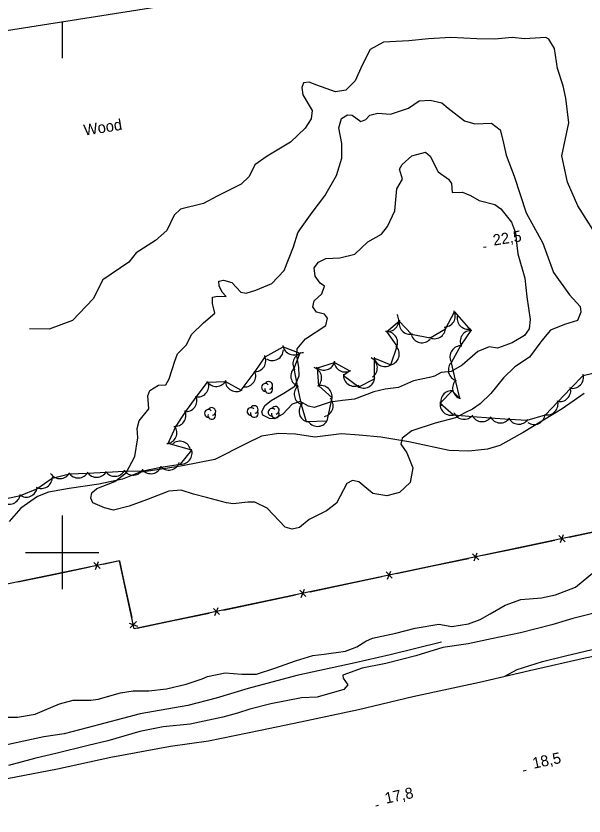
# Model space of a CAD drawing. Extents: x 643342 to 646936, y 5873857 to 5876103.
# Drawn here: x 645787.4 to 645941.9, y 5875728.4 to 5875945.7 of the extents above; entities that cross this region are included whole.
import ezdxf

# ---------------------------------------------------------------- set-up
doc = ezdxf.new("R2010")
doc.units = 0
for name, color, linetype in [('Niveau 1', 7, 'Continuous'), ('Niveau 2', 7, 'Continuous'), ('Niveau 22', 7, 'Continuous'), ('Niveau 25', 7, 'Continuous'), ('Niveau 3', 7, 'Continuous'), ('Niveau 37', 7, 'Continuous'), ('Niveau 4', 7, 'Continuous'), ('Niveau 44', 7, 'Continuous'), ('Niveau 60', 7, 'Continuous'), ('Niveau 61', 7, 'Continuous')]:
    doc.layers.add(name, color=color, linetype=linetype)

msp = doc.modelspace()

# ---------------------------------------------------------------- linework, layer by layer
at = {"layer": 'Niveau 1'}
for points in [[(645871.64, 5875879.82), (645875.45, 5875880.05), (645879.53, 5875881.06), (645883.06, 5875884.39), (645886.85, 5875886.41), (645888.41, 5875888.55), (645890.45, 5875892.76), (645890.95, 5875898.78), (645892.52, 5875901.37), (645891.69, 5875904.12), (645892.42, 5875905.42), (645895.01, 5875907.78), (645898.74, 5875908.75), (645900.08, 5875907.68), (645902.18, 5875903.38), (645905.02, 5875901.37), (645905.85, 5875900.18), (645906.06, 5875897.77), (645908.78, 5875897.89), (645911.03, 5875896.97), (645913.34, 5875895.59), (645917.58, 5875894.54), (645919.29, 5875893.33), (645922.19, 5875889.75), (645923.21, 5875886.79), (645923.59, 5875883.41), (645923.84, 5875881.12), (645925.74, 5875874.49), (645926.31, 5875869.39), (645927.22, 5875863.28), (645926.98, 5875860.76), (645925.72, 5875858.95), (645922.29, 5875856.9), (645918.37, 5875855.5), (645916.06, 5875855.84), (645913.01, 5875854.53), (645908.7, 5875850.88), (645905.75, 5875849.12), (645903.05, 5875848.83), (645901.23, 5875847.89), (645899.88, 5875847.51)], [(645899.88, 5875847.51), (645895.5, 5875846.58), (645891.39, 5875844.75), (645887.77, 5875844.37), (645884.71, 5875843.58), (645879.51, 5875841.64), (645876.18, 5875841.23), (645872.86, 5875840.76), (645868.53, 5875839.37), (645866.92, 5875839.72), (645864.69, 5875840.94), (645862.55, 5875840.3), (645860, 5875837.54), (645857.64, 5875836.24), (645856.35, 5875836.34), (645854.51, 5875837.24), (645854.29, 5875838.15), (645855.09, 5875839.92), (645856.8, 5875841.26), (645860.25, 5875843.25), (645863.23, 5875845.19), (645864.38, 5875847.98), (645864.3, 5875850.29), (645863.78, 5875853.42), (645863.87, 5875855.29), (645866.13, 5875858.02), (645871.67, 5875861.62), (645872.15, 5875863.59), (645871.32, 5875864.72), (645869.17, 5875865.24), (645868.13, 5875866.75), (645868.49, 5875868.3), (645870.6, 5875870.2), (645871.3, 5875872.36), (645870.16, 5875873.17), (645868.79, 5875875), (645868.48, 5875877.34), (645869.71, 5875878.8), (645871.64, 5875879.82)]]:
    msp.add_lwpolyline(points, dxfattribs=at)
at = {"layer": 'Niveau 2'}
for points in [[(645946.64, 5875884.03), (645940.15, 5875894.15), (645937.33, 5875900.59), (645935.83, 5875907.75), (645937.76, 5875916.66), (645936.89, 5875923.36), (645936.22, 5875926.77), (645934.66, 5875931.43), (645933.87, 5875936.91), (645932.25, 5875939.41), (645931.44, 5875939.85), (645925.65, 5875939.52), (645922.35, 5875939.87), (645917.49, 5875939.47), (645912.76, 5875939.55), (645905.61, 5875939.89), (645899.59, 5875939.49), (645894.23, 5875938.98), (645887.39, 5875938.6), (645883.76, 5875936.65), (645881.55, 5875932.41), (645879.63, 5875928.15), (645877.11, 5875925.62), (645874.31, 5875925.09), (645869.2, 5875926.98), (645867.14, 5875927.75), (645865.64, 5875927.54), (645865.14, 5875926.26), (645865.41, 5875924.32), (645867.93, 5875920.06), (645867.65, 5875917.82), (645866.07, 5875915.22), (645862.11, 5875911.49), (645855.71, 5875907.62), (645852.35, 5875905.29), (645850.83, 5875902.11), (645848.66, 5875900.08), (645842.14, 5875896.77), (645838.45, 5875894.81), (645832.15, 5875893.21), (645830.4, 5875891.58), (645828.41, 5875887.41), (645825.37, 5875884.77), (645820.09, 5875881.36), (645818.15, 5875878.83), (645811.03, 5875874.06), (645808.39, 5875868.84), (645802.84, 5875862.97), (645796.5, 5875860.66), (645791.09, 5875860.76)], [(645840.89, 5875869.31), (645842.25, 5875869.62), (645844.6, 5875869.47), (645843.48, 5875870.68), (645842.7, 5875872.4), (645842.57, 5875873.66), (645843.81, 5875873.97), (645846.1, 5875873.28), (645848.54, 5875870.7), (645850.03, 5875870.45), (645852.68, 5875871.25), (645856.97, 5875873.04), (645860.36, 5875876.59), (645862.86, 5875883.01), (645864.07, 5875886.85), (645864.82, 5875887.92), (645867.95, 5875892.37), (645871.4, 5875896.91), (645874.53, 5875902.4), (645875.99, 5875907.08), (645876.01, 5875911.08), (645875.25, 5875915.35), (645875.96, 5875917.92), (645877.54, 5875918.84), (645878.83, 5875918.8), (645881.17, 5875917.08), (645882.58, 5875917.57), (645883.66, 5875918.79), (645885.81, 5875919.37), (645889.28, 5875919.04), (645894.16, 5875920.72), (645897.03, 5875922.7), (645900.03, 5875922.9), (645903.21, 5875922.14), (645904.94, 5875920.7), (645909.33, 5875917.28), (645912.22, 5875916.43), (645916.74, 5875916.62), (645919.04, 5875914.77), (645919.82, 5875911.96), (645920.74, 5875907.88), (645922.89, 5875902.19), (645926.09, 5875892.21), (645930.62, 5875883.99), (645933.6, 5875876.06), (645937.95, 5875869.96), (645940.81, 5875866.78), (645940.98, 5875865.24), (645940.12, 5875863), (645936.51, 5875861.92), (645932.72, 5875860.41), (645930.35, 5875857.6), (645927.07, 5875853.02), (645923.04, 5875850.44), (645919.94, 5875847.38), (645916.57, 5875843.13), (645913.62, 5875840.32), (645911.56, 5875838.88), (645909.61, 5875838.04)], [(645909.61, 5875838.04), (645906.92, 5875836.59), (645901.37, 5875835.13), (645895.06, 5875833.06), (645892.43, 5875831.04), (645892.03, 5875829.37), (645893.69, 5875827.05), (645895.31, 5875822.98), (645894.64, 5875818.95), (645891.73, 5875816.26), (645888.28, 5875815.31), (645884.47, 5875816.01), (645880.62, 5875819.15), (645878.95, 5875819.5), (645877.4, 5875818.75), (645874.56, 5875813.33), (645871.87, 5875811.3), (645867.11, 5875808.94), (645864.5, 5875806.74), (645862.5, 5875806.3), (645860.58, 5875806.85), (645855.76, 5875811.98), (645852.37, 5875813.59), (645850.44, 5875813.62), (645846.47, 5875813.2), (645844.69, 5875813.48), (645839.23, 5875814.87), (645835.74, 5875815.78), (645832.36, 5875816.88), (645829, 5875816.64), (645822.91, 5875814.25), (645818.2, 5875812.52), (645813.94, 5875811.49), (645811.54, 5875812.11), (645808.36, 5875813.46), (645807.81, 5875814.68), (645808.06, 5875816.16), (645809.39, 5875817.35), (645814.31, 5875819.26), (645817.38, 5875821.57), (645819.75, 5875826.06), (645820.54, 5875831.08), (645820.38, 5875833.62), (645820.97, 5875835.72), (645823.52, 5875839.01), (645823.31, 5875842.53), (645823.79, 5875843.98), (645826.14, 5875845.39), (645828.17, 5875845.54), (645829.1, 5875847.1), (645830.61, 5875851.96), (645831.39, 5875853.9), (645833.79, 5875856.42), (645835.18, 5875859.18), (645838.39, 5875862.37), (645841.48, 5875865.01), (645840.9, 5875867.57), (645840.89, 5875869.31)], [(645934.1, 5875788.41), (645939.53, 5875790.56), (645944.73, 5875794.78)], [(645780.99, 5875755.24), (645787.89, 5875755.21), (645792.66, 5875756.01), (645795.22, 5875757.16), (645799.25, 5875758.81), (645803, 5875759.79), (645807.79, 5875759.83), (645809.81, 5875760.11), (645815.81, 5875761.85), (645819.32, 5875762.4), (645823.59, 5875762.33), (645828.38, 5875762.95), (645833.73, 5875764.22), (645838.02, 5875765.67), (645839.53, 5875766.3), (645844.33, 5875767.27), (645848.81, 5875766.93), (645852.85, 5875766.89), (645857.81, 5875768.53), (645863.44, 5875770.53), (645868.12, 5875772.01), (645871.18, 5875772.34), (645877.06, 5875773.14), (645880.14, 5875774.34), (645882.54, 5875775.88), (645884.38, 5875776.71), (645890.66, 5875778.08), (645896, 5875779.41), (645902.43, 5875780.5), (645905.95, 5875779.88), (645910.43, 5875780.53), (645913.63, 5875781.74), (645916.38, 5875783.32), (645920.39, 5875785.61), (645924.71, 5875787.23), (645930.33, 5875787.66), (645934.1, 5875788.41)], [(645948.47, 5875784.47), (645938.86, 5875782.05), (645933.09, 5875780.33), (645924.63, 5875778.09), (645916.74, 5875776.49), (645910.4, 5875775.18), (645903.5, 5875774.15), (645896.16, 5875771.86), (645887.97, 5875769.76), (645881.51, 5875768.49)], [(645920.33, 5875766.37), (645923.7, 5875768.19), (645930.58, 5875770.38), (645936.83, 5875771.91), (645945.59, 5875773.95)], [(645881.51, 5875768.49), (645876.33, 5875766.66), (645876.37, 5875765.79), (645877.68, 5875764.01), (645876.59, 5875762.72), (645869.28, 5875760.66), (645865.03, 5875760.5), (645856.68, 5875758.8), (645851.05, 5875757.39), (645847.63, 5875756.31), (645843.65, 5875755.25), (645834.83, 5875753.29), (645827.48, 5875752.57), (645821.13, 5875751.31), (645812.4, 5875748.81), (645807.1, 5875747.55), (645798.28, 5875745.33), (645792.86, 5875744.11), (645785.42, 5875742.09)]]:
    msp.add_lwpolyline(points, dxfattribs=at)
at = {"layer": 'Niveau 22'}
for points in [[(645941.92, 5875843.13), (645935.96, 5875839), (645925.36, 5875832.52), (645918.97, 5875829.05), (645915.59, 5875828), (645910.51, 5875827.46), (645905.23, 5875827.71), (645894.24, 5875830.03), (645886.63, 5875831.32), (645880.74, 5875831.86), (645875.93, 5875832.16), (645868.69, 5875831.27), (645863.47, 5875832.11), (645858.79, 5875832.31), (645854.21, 5875831.6), (645849.89, 5875829.51), (645841.5, 5875825.25), (645832.72, 5875823.51), (645825.84, 5875822.43), (645820.91, 5875821.67), (645816.44, 5875819.92), (645809.94, 5875818.53), (645801.91, 5875817.33), (645796.29, 5875816.39), (645793.28, 5875815.14), (645788.72, 5875811.98)], [(645788.72, 5875811.98), (645785.61, 5875808.39)]]:
    msp.add_lwpolyline(points, dxfattribs=at)
at = {"layer": 'Niveau 25'}
msp.add_lwpolyline([(645735, 5875727.48), (645752.7, 5875731.47), (645770.29, 5875735.32), (645782.61, 5875738.14), (645798.77, 5875741.14), (645813.27, 5875744.32), (645829.42, 5875747.32), (645839.78, 5875748.77), (645853.95, 5875751.67), (645864.79, 5875753.99), (645880.55, 5875757.3), (645895.34, 5875760.85), (645913.48, 5875764.76), (645927.02, 5875767.94), (645942.17, 5875771.3), (645957.91, 5875774.6), (645975.77, 5875778.71), (645993.69, 5875783.29), (646008.47, 5875786.72)], dxfattribs=at)
at = {"layer": 'Niveau 3'}
for p, q in [((645914.49, 5875882.92), (645915.28, 5875883.04)), ((645925.35, 5875740.63), (645926.14, 5875740.8)), ((645885.23, 5875731.13), (645886.01, 5875731.3))]:
    msp.add_line(p, q, dxfattribs=at)
at = {"layer": 'Niveau 37'}
for points in [[(646156.26, 5875850.21), (646086.41, 5875835.45), (645993.12, 5875815.85), (645903.06, 5875796.81), (645819.6, 5875779.21), (645815.58, 5875797.71), (645725.88, 5875779.09), (645656.81, 5875764.27)], [(645935.44, 5875802.63), (645936.3, 5875804.85)], [(645937.81, 5875804.15), (645947.6, 5875806.22)], [(645924.12, 5875801.26), (645933.9, 5875803.33)], [(645935.02, 5875804.58), (645936.71, 5875802.9)], [(645914.33, 5875799.19), (645924.12, 5875801.26)], [(645900.64, 5875796.29), (645910.42, 5875798.36)], [(645911.54, 5875799.62), (645913.23, 5875797.94)], [(645911.96, 5875797.67), (645912.82, 5875799.89)], [(645808.63, 5875797.28), (645810.3, 5875795.59)], [(645809.03, 5875795.33), (645809.9, 5875797.55)], [(645811.14, 5875796.81), (645815.58, 5875797.74)], [(645815.58, 5875797.71), (645816.8, 5875792.09)], [(645890.85, 5875794.23), (645900.64, 5875796.29)], [(645787.91, 5875791.96), (645797.71, 5875794)], [(645797.71, 5875794), (645807.5, 5875796.03)], [(645888.06, 5875794.66), (645889.75, 5875792.98)], [(645888.47, 5875792.71), (645889.33, 5875794.93)], [(645816.8, 5875792.09), (645818.92, 5875782.32)], [(645877.15, 5875791.34), (645886.94, 5875793.41)], [(645864.58, 5875789.71), (645866.26, 5875788.03)], [(645864.99, 5875787.76), (645865.85, 5875789.98)], [(645867.37, 5875789.28), (645877.15, 5875791.34)], [(645853.67, 5875786.39), (645863.45, 5875788.46)], [(645843.88, 5875784.33), (645853.67, 5875786.39)], [(645830.19, 5875781.44), (645839.97, 5875783.5)], [(645841.1, 5875784.76), (645842.78, 5875783.08)], [(645841.51, 5875782.81), (645842.37, 5875785.03)], [(645820.19, 5875781.2), (645818.51, 5875779.51)], [(645820.4, 5875779.38), (645830.19, 5875781.44)], [(645818.24, 5875780.78), (645820.47, 5875779.93)]]:
    msp.add_lwpolyline(points, dxfattribs=at)
at = {"layer": 'Niveau 4'}
msp.add_lwpolyline([(645903.13, 5875775.55), (645889.12, 5875772.19), (645879.65, 5875770.02), (645863.77, 5875766.58), (645850.6, 5875762.97), (645841.87, 5875760.41), (645834.13, 5875758.42), (645821.16, 5875756.1), (645806.82, 5875752.36), (645800.57, 5875750.65), (645795.05, 5875749.83), (645782.01, 5875747.04), (645778.4, 5875745.72), (645775.4, 5875745.4), (645766.19, 5875743.96), (645758.88, 5875742.25), (645744.54, 5875739.56), (645733.3, 5875737.43), (645718.22, 5875733.96), (645705.61, 5875731.45), (645698.18, 5875729.73), (645684.8, 5875726.78)], dxfattribs=at)
at = {"layer": 'Niveau 44'}
for points in [[(645894.99, 5875859.28), (645900.02, 5875858.29), (645904.19, 5875860.77), (645906.64, 5875865.37), (645911.07, 5875860.29), (645908.38, 5875856.25), (645905.71, 5875851.47), (645906.82, 5875846.74), (645907.97, 5875841.87), (645905.99, 5875843.92), (645902.75, 5875840.54), (645906.38, 5875837.32), (645911.6, 5875836.92), (645916.45, 5875836.58), (645921.58, 5875836.22), (645926.42, 5875835.88), (645931.4, 5875837.35), (645934.74, 5875840.87), (645938.3, 5875844.58), (645941.67, 5875848.08), (645946.85, 5875849.28)], [(645783.62, 5875814.38), (645788.65, 5875815.44), (645793.14, 5875817.3), (645797.32, 5875820.15), (645802.01, 5875821.36), (645806.86, 5875821.54), (645812.01, 5875821.75), (645816.85, 5875822.05), (645822.05, 5875822.17), (645826.81, 5875823.12), (645832.12, 5875823.99), (645835.23, 5875827.72), (645828.8, 5875829.59), (645830.79, 5875834.01), (645833.58, 5875838.24), (645836.45, 5875842.16), (645839.55, 5875846.21), (645844.4, 5875846.45), (645848.67, 5875844.02), (645852.5, 5875849.1), (645855.18, 5875853.15), (645860.09, 5875855.85), (645864.62, 5875854.11), (645862.96, 5875849.98), (645863.86, 5875845.21), (645865.01, 5875840.18), (645866.37, 5875835.52), (645872.02, 5875835.73), (645873.35, 5875842), (645869.74, 5875845.24), (645869.38, 5875850.1), (645874.01, 5875851.55), (645878.2, 5875849.28), (645876.47, 5875848.08), (645880.61, 5875844.93), (645884.93, 5875847.14), (645884.86, 5875852.73), (645889.37, 5875850.96), (645891.04, 5875856.04), (645888.23, 5875860), (645891.64, 5875862.79), (645894.99, 5875859.28)]]:
    msp.add_lwpolyline(points, dxfattribs=at)
for centre, radius, start, end in [((645903.87, 5875864.22), 3, 268.5868, 28.5647), ((645903.87, 5875864.22), 3, 268.5868, 28.5647), ((645903.87, 5875864.22), 3, 268.5868, 28.5647), ((645888.51, 5875863), 3, 273.2391, 33.217), ((645888.51, 5875863), 3, 273.2391, 33.217), ((645888.51, 5875863), 3, 273.2391, 33.217), ((645910.34, 5875863.62), 3, 163.6389, 283.6168), ((645910.34, 5875863.62), 3, 163.6389, 283.6168), ((645910.34, 5875863.62), 3, 163.6389, 283.6168), ((645894.59, 5875862.25), 3, 163.6761, 283.6541), ((645894.59, 5875862.25), 3, 163.6761, 283.6541), ((645894.59, 5875862.25), 3, 163.6761, 283.6541), ((645888.19, 5875857), 3, 335.401, 95.379), ((645888.19, 5875857), 3, 335.401, 95.379), ((645888.19, 5875857), 3, 335.401, 95.379), ((645901.2, 5875861.04), 3, 240.8288, 0.8068), ((645901.2, 5875861.04), 3, 240.8288, 0.8068), ((645901.2, 5875861.04), 3, 240.8288, 0.8068), ((645911.19, 5875857.29), 3, 86.3436, 206.3216), ((645911.19, 5875857.29), 3, 86.3436, 206.3216), ((645911.19, 5875857.29), 3, 86.3436, 206.3216), ((645897.8, 5875859.95), 3, 197.1344, 317.1124), ((645897.8, 5875859.95), 3, 197.1344, 317.1124), ((645897.8, 5875859.95), 3, 197.1344, 317.1124), ((645857.16, 5875855.12), 3, 238.1313, 358.1093), ((645857.16, 5875855.12), 3, 238.1313, 358.1093), ((645857.16, 5875855.12), 3, 238.1313, 358.1093), ((645862.98, 5875856.63), 3, 189.0379, 309.0159), ((645862.98, 5875856.63), 3, 189.0379, 309.0159), ((645862.98, 5875856.63), 3, 189.0379, 309.0159), ((645888.65, 5875853.87), 3, 286.9533, 46.9312), ((645888.65, 5875853.87), 3, 286.9533, 46.9312), ((645888.65, 5875853.87), 3, 286.9533, 46.9312), ((645908.42, 5875853.13), 3, 86.3436, 206.3216), ((645908.42, 5875853.13), 3, 86.3436, 206.3216), ((645908.42, 5875853.13), 3, 86.3436, 206.3216), ((645852.37, 5875852.1), 3, 266.5586, 26.5366), ((645852.37, 5875852.1), 3, 266.5586, 26.5366), ((645852.37, 5875852.1), 3, 266.5586, 26.5366), ((645865.73, 5875851.23), 3, 92.6679, 212.6459), ((645865.73, 5875851.23), 3, 92.6679, 212.6459), ((645865.73, 5875851.23), 3, 92.6679, 212.6459), ((645882.68, 5875850.13), 3, 303.3789, 63.3568), ((645882.68, 5875850.13), 3, 303.3789, 63.3568), ((645882.68, 5875850.13), 3, 303.3789, 63.3568), ((645887.76, 5875853.49), 3, 188.557, 308.535), ((645887.76, 5875853.49), 3, 188.557, 308.535), ((645887.76, 5875853.49), 3, 188.557, 308.535), ((645871.17, 5875852.51), 3, 227.3613, 347.3393), ((645871.17, 5875852.51), 3, 227.3613, 347.3393), ((645871.17, 5875852.51), 3, 227.3613, 347.3393), ((645876.92, 5875852), 3, 181.2468, 301.2247), ((645876.92, 5875852), 3, 181.2468, 301.2247), ((645876.92, 5875852), 3, 181.2468, 301.2247), ((645907.98, 5875849.51), 3, 133.2394, 253.2173), ((645907.98, 5875849.51), 3, 133.2394, 253.2173), ((645907.98, 5875849.51), 3, 133.2394, 253.2173), ((645849.61, 5875847.92), 3, 266.5586, 26.5366), ((645849.61, 5875847.92), 3, 266.5586, 26.5366), ((645849.61, 5875847.92), 3, 266.5586, 26.5366), ((645865.15, 5875847.92), 3, 130.6612, 250.6391), ((645865.15, 5875847.92), 3, 130.6612, 250.6391), ((645865.15, 5875847.92), 3, 130.6612, 250.6391), ((645867.52, 5875847.38), 3, 310.7379, 70.7159), ((645867.52, 5875847.38), 3, 310.7379, 70.7159), ((645867.52, 5875847.38), 3, 310.7379, 70.7159), ((645879.46, 5875848.12), 3, 174.7108, 294.6888), ((645879.46, 5875848.12), 3, 174.7108, 294.6888), ((645879.46, 5875848.12), 3, 174.7108, 294.6888), ((645938.71, 5875847.55), 3, 256.1494, 16.1273), ((645938.71, 5875847.55), 3, 256.1494, 16.1273), ((645938.71, 5875847.55), 3, 256.1494, 16.1273), ((645836.86, 5875845.22), 3, 257.8089, 17.7868), ((645836.86, 5875845.22), 3, 257.8089, 17.7868), ((645836.86, 5875845.22), 3, 257.8089, 17.7868), ((645841.89, 5875848.09), 3, 212.8172, 332.7952), ((645841.89, 5875848.09), 3, 212.8172, 332.7952), ((645841.89, 5875848.09), 3, 212.8172, 332.7952), ((645847.33, 5875846.7), 3, 182.5344, 302.5124), ((645847.33, 5875846.7), 3, 182.5344, 302.5124), ((645847.33, 5875846.7), 3, 182.5344, 302.5124), ((645856.15, 5875845.34), 1.05, 282.2692, 149.7263), ((645881.97, 5875847.61), 3, 237.0883, 357.0663), ((645881.97, 5875847.61), 3, 237.0883, 357.0663), ((645881.97, 5875847.61), 3, 237.0883, 357.0663), ((645909.13, 5875844.64), 3, 133.2394, 253.2173), ((645909.13, 5875844.64), 3, 133.2394, 253.2173), ((645909.13, 5875844.64), 3, 133.2394, 253.2173), ((645855.25, 5875844.81), 1.05, 44.1154, 269.804), ((645856.15, 5875844.29), 1.05, 166.9369, 29.6212), ((645866.07, 5875843.01), 3, 130.6612, 250.6391), ((645866.07, 5875843.01), 3, 130.6612, 250.6391), ((645866.07, 5875843.01), 3, 130.6612, 250.6391), ((645870.36, 5875842.31), 3, 348.0533, 108.0312), ((645870.36, 5875842.31), 3, 348.0533, 108.0312), ((645870.36, 5875842.31), 3, 348.0533, 108.0312), ((645905.9, 5875840.92), 3, 82.3567, 202.3346), ((645905.9, 5875840.92), 3, 82.3567, 202.3346), ((645905.9, 5875840.92), 3, 82.3567, 202.3346), ((645935.25, 5875843.95), 3, 256.1494, 16.1273), ((645935.25, 5875843.95), 3, 256.1494, 16.1273), ((645935.25, 5875843.95), 3, 256.1494, 16.1273), ((645833.6, 5875841.24), 3, 263.7728, 23.7507), ((645833.6, 5875841.24), 3, 263.7728, 23.7507), ((645833.6, 5875841.24), 3, 263.7728, 23.7507), ((645870.66, 5875839.85), 3, 283.2232, 43.2012), ((645870.66, 5875839.85), 3, 283.2232, 43.2012), ((645870.66, 5875839.85), 3, 283.2232, 43.2012), ((645852.23, 5875838.8), 1.05, 282.2692, 149.7263), ((645857.94, 5875838.59), 1.05, 282.2692, 149.7263), ((645867.39, 5875838.34), 3, 136.1943, 256.1723), ((645867.39, 5875838.34), 3, 136.1943, 256.1723), ((645867.39, 5875838.34), 3, 136.1943, 256.1723), ((645905.73, 5875840.25), 3, 168.3669, 288.3448), ((645905.73, 5875840.25), 3, 168.3669, 288.3448), ((645905.73, 5875840.25), 3, 168.3669, 288.3448), ((645931.79, 5875840.32), 3, 256.5833, 16.5612), ((645931.79, 5875840.32), 3, 256.5833, 16.5612), ((645931.79, 5875840.32), 3, 256.5833, 16.5612), ((645830.64, 5875837.21), 3, 263.7728, 23.7507), ((645830.64, 5875837.21), 3, 263.7728, 23.7507), ((645830.64, 5875837.21), 3, 263.7728, 23.7507), ((645839.78, 5875837.74), 1.05, 44.1154, 269.804), ((645840.68, 5875837.22), 1.05, 166.9369, 29.6212), ((645840.68, 5875838.27), 1.05, 282.2692, 149.7263), ((645851.33, 5875838.27), 1.05, 44.1154, 269.804), ((645852.23, 5875837.75), 1.05, 166.9369, 29.6212), ((645857.04, 5875838.06), 1.05, 44.1154, 269.804), ((645857.94, 5875837.54), 1.05, 166.9369, 29.6212), ((645909.28, 5875839.14), 3, 202.432, 322.41), ((645909.28, 5875839.14), 3, 202.432, 322.41), ((645909.28, 5875839.14), 3, 202.432, 322.41), ((645928.29, 5875837.73), 3, 235.1539, 355.1318), ((645928.29, 5875837.73), 3, 235.1539, 355.1318), ((645928.29, 5875837.73), 3, 235.1539, 355.1318), ((645869.42, 5875837.23), 3, 216.0779, 336.0558), ((645869.42, 5875837.23), 3, 216.0779, 336.0558), ((645869.42, 5875837.23), 3, 216.0779, 336.0558), ((645914.15, 5875838.51), 3, 205.9737, 325.9516), ((645914.15, 5875838.51), 3, 205.9737, 325.9516), ((645914.15, 5875838.51), 3, 205.9737, 325.9516), ((645919.14, 5875838.16), 3, 205.9737, 325.9516), ((645919.14, 5875838.16), 3, 205.9737, 325.9516), ((645919.14, 5875838.16), 3, 205.9737, 325.9516), ((645924.12, 5875837.81), 3, 205.9737, 325.9516), ((645924.12, 5875837.81), 3, 205.9737, 325.9516), ((645924.12, 5875837.81), 3, 205.9737, 325.9516), ((645828.18, 5875832.53), 3, 275.7711, 35.749), ((645828.18, 5875832.53), 3, 275.7711, 35.749), ((645828.18, 5875832.53), 3, 275.7711, 35.749), ((645831.97, 5875827.2), 3, 11.0625, 131.0405), ((645831.97, 5875827.2), 3, 11.0625, 131.0405), ((645831.97, 5875827.2), 3, 11.0625, 131.0405), ((645832.32, 5875826.99), 3, 260.1003, 20.0782), ((645832.32, 5875826.99), 3, 260.1003, 20.0782), ((645832.32, 5875826.99), 3, 260.1003, 20.0782), ((645828.99, 5875825.34), 3, 221.1937, 341.1716), ((645828.99, 5875825.34), 3, 221.1937, 341.1716), ((645828.99, 5875825.34), 3, 221.1937, 341.1716), ((645814.32, 5875823.66), 3, 213.5308, 333.5087), ((645814.32, 5875823.66), 3, 213.5308, 333.5087), ((645814.32, 5875823.66), 3, 213.5308, 333.5087), ((645819.31, 5875823.97), 3, 213.5308, 333.5087), ((645819.31, 5875823.97), 3, 213.5308, 333.5087), ((645819.31, 5875823.97), 3, 213.5308, 333.5087), ((645824.09, 5875824.37), 3, 221.1937, 341.1716), ((645824.09, 5875824.37), 3, 221.1937, 341.1716), ((645824.09, 5875824.37), 3, 221.1937, 341.1716), ((645794.33, 5875820.36), 3, 241.9118, 1.8898), ((645794.33, 5875820.36), 3, 241.9118, 1.8898), ((645794.33, 5875820.36), 3, 241.9118, 1.8898), ((645799.38, 5875823.03), 3, 212.0468, 332.0247), ((645799.38, 5875823.03), 3, 212.0468, 332.0247), ((645799.38, 5875823.03), 3, 212.0468, 332.0247), ((645804.37, 5875823.21), 3, 212.0468, 332.0247), ((645804.37, 5875823.21), 3, 212.0468, 332.0247), ((645804.37, 5875823.21), 3, 212.0468, 332.0247), ((645809.37, 5875823.39), 3, 212.0468, 332.0247), ((645809.37, 5875823.39), 3, 212.0468, 332.0247), ((645809.37, 5875823.39), 3, 212.0468, 332.0247), ((645785.6, 5875816.08), 3, 232.5507, 352.5286), ((645785.6, 5875816.08), 3, 232.5507, 352.5286), ((645785.6, 5875816.08), 3, 232.5507, 352.5286), ((645790.22, 5875818), 3, 232.5507, 352.5286), ((645790.22, 5875818), 3, 232.5507, 352.5286), ((645790.22, 5875818), 3, 232.5507, 352.5286)]:
    msp.add_arc(centre, radius, start, end, dxfattribs=at)
at = {"layer": 'Niveau 60'}
msp.add_line((645800, 5875944.25), (645800, 5875934.25), dxfattribs=at)
msp.add_lwpolyline([(643367.26, 5875561.52), (646133.22, 5875996.67), (646397.42, 5874317.29), (643631.46, 5873882.15)], close=True, dxfattribs=at)
at = {"layer": 'Niveau 61'}
for points in [[(645800, 5875810), (645800, 5875800), (645800, 5875790)], [(645790, 5875800), (645800, 5875800), (645810, 5875800)]]:
    msp.add_lwpolyline(points, dxfattribs=at)

# ---------------------------------------------------------------- texts
at = {"layer": 'Niveau 3'}
for s, rotation, p in [('22,5 ', 8.9405, (645917.34, 5875883.33)), ('18,5 ', 11.9246, (645928.18, 5875741.19)), ('17,8 ', 11.9246, (645888.06, 5875731.69))]:
    msp.add_text(s, height=3, rotation=rotation, dxfattribs=at).set_placement(p)
at = {"layer": 'Niveau 44'}
msp.add_text('Wood', height=3, rotation=8.9405, dxfattribs=at).set_placement((645806.1, 5875913.2))

doc.saveas('drawing.dxf')
